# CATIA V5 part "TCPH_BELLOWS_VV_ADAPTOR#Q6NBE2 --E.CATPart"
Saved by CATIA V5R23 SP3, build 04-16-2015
Part number: TCPH_BELLOWS_VV_ADAPTOR#Q6NBDM
Revision: --E
Nomenclature: _
Description: TCPH_BELLOWS_VV_ADAPTOR
Property "AT": "PD"
Property "REP": "CM"
Property "External Part ID": "_"
Property "Description Modification": "FDRModel"
Property "PREF": "Y"
Property "LONG": "_"
Property "PBS 1": "24"
Property "PBS 2": "CR"
Property "PBS 3": "LC"
Property "DEPT": "_"
Property "DIVN": "_"
Property "GROUP": "_"
Property "UNIT": "_"
Property "PARTY": "_"
Property "RO": "IOKIK"
Property "RE": "VITUPIG"
Property "PRO": "---"
Property "Change Type": "Major"
Property "Maturity Level": "CD"
Property "Export Number": "_"
Property "Description Documents": "_"
Property "BOM": "_"
Property "ID": "Q6NBDM"
Property "User In Enovia": "VAUQUEJ"
Property "Object Type": "_"
Property "CADENAS_ID": "_"
Property "Life Cycle Status": "Approved"
Material "X2CrNi18-09 1.4307 (304L)": density 8000 kg/m3, Young's modulus 1.93e+11 Pa, Poisson ratio 0.3, thermal expansion 1.6e-05 1/K
Bounding box of the stored display mesh (mm): x 12840 to 12950, y -574.84 to 574.84, z -4967.656 to -3818.344
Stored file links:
  C:\Users\pandeym\Desktop\__TCPH\TCPH_BELLOWS_VV_ADAPTOR#Q6NBE2 --E.CATPart
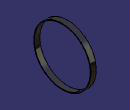
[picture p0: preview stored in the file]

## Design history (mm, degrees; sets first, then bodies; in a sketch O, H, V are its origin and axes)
Set1
  Line1 "CRYOPUMP_CENTER_AXIS": linked copy from another document
  Sketch1 "BELLOWS_VV_ADAPTOR", origin (0, 0, 0), H (-1, 0, 0), V (0, 0, 1), geometry linked from another document
Body1 (main body)
  Shaft1: profile Sketch1, axis Line1, angle 360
